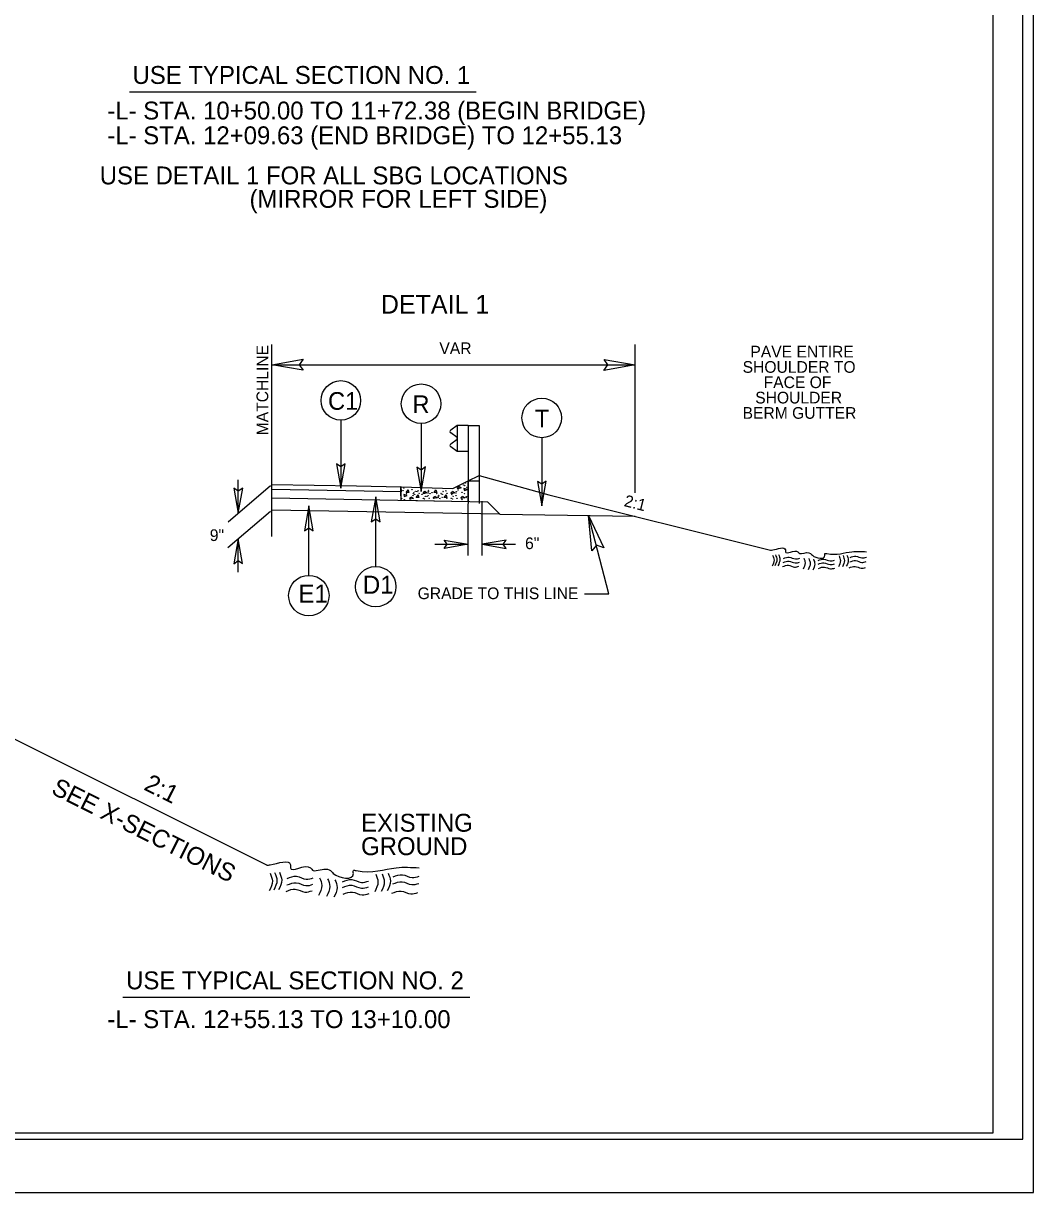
# Model space of a CAD drawing. Extents: x 575722 to 576066, y -53107 to -52774.
# Drawn here: x 575923.44 to 575965.78, y -53106.87 to -53057.85 of the extents above; entities that cross this region are included whole.
import ezdxf

# ---------------------------------------------------------------- set-up
doc = ezdxf.new("R2010")
doc.units = 0
for name, color, linetype in [('Old_Level_1', 7, 'Continuous'), ('Old_Level_11', 7, 'Continuous'), ('Old_Level_2', 7, 'Continuous'), ('Old_Level_20', 7, 'Continuous'), ('Old_Level_21', 7, 'Continuous'), ('Old_Level_3', 7, 'Continuous'), ('Prop Dimension Text', 7, 'Continuous'), ('Prop DSN Text', 7, 'Continuous'), ('Prop Terminator CELL', 7, 'Continuous'), ('Sheet Cutting Line CELL', 7, 'Continuous'), ('Sheet Plot Border Inside CELL', 7, 'Continuous'), ('Sheet Plot Border Outside CELL', 7, 'Continuous'), ('Sheet Typical CELL', 7, 'Continuous'), ('Typical Curb CELL', 7, 'Continuous'), ('Typical Guardrail CELL', 7, 'Continuous'), ('Typical Slope Point Local CELL', 7, 'Continuous'), ('Typical Terminator CELL', 7, 'Continuous'), ('Typical Text Grade Point CELL', 7, 'Continuous')]:
    doc.layers.add(name, color=color, linetype=linetype)

msp = doc.modelspace()

# ---------------------------------------------------------------- linework, layer by layer
at = {"layer": 'Old_Level_1'}
for p, q in [((575933.856, -53077.395), (575933.856, -53077.185)), ((575933.856, -53077.185), (575937.408, -53077.245)), ((575942.087, -53077.033), (575942.551, -53076.801)), ((575942.551, -53076.801), (575945.467, -53077.611)), ((575939.271, -53077.488), (575933.856, -53077.395)), ((575939.268, -53077.276), (575939.268, -53077.854)), ((575945.467, -53077.611), (575954.759, -53079.934)), ((575942.908, -53077.917), (575933.856, -53077.76)), ((575942.908, -53077.917), (575943.413, -53078.421)), ((575943.413, -53078.421), (575933.856, -53078.256)), ((575943.413, -53078.421), (575949.089, -53078.516))]:
    msp.add_line(p, q, dxfattribs=at)
msp.add_lwpolyline([(575937.408, -53077.245), (575939.268, -53077.276), (575939.271, -53077.488)], dxfattribs=at)
at = {"layer": 'Old_Level_11'}
for p, q in [((575942.087, -53080.152), (575942.087, -53077.987)), ((575942.666, -53080.152), (575942.666, -53077.885))]:
    msp.add_line(p, q, dxfattribs=at)
for points in [[(575932.269, -53077.338), (575932.449, -53078.383), (575932.635, -53077.332), (575932.449, -53077.465)], [(575932.269, -53077.338), (575932.449, -53078.383), (575932.635, -53077.332), (575932.449, -53077.465)], [(575932.629, -53080.5), (575932.449, -53079.454), (575932.263, -53080.506), (575932.449, -53080.372)], [(575932.629, -53080.5), (575932.449, -53079.454), (575932.263, -53080.506), (575932.449, -53080.372)]]:
    msp.add_lwpolyline(points, close=True, dxfattribs=at)
at = {"layer": 'Old_Level_2'}
for points in [[(575954.759, -53079.934), (575954.849, -53079.924), (575955.377, -53079.924), (575955.377, -53080), (575955.905, -53080), (575955.981, -53080.075), (575956.056, -53080.075), (575956.434, -53080.075), (575956.509, -53080.151), (575957.037, -53080.151), (575957.037, -53080.075), (575957.113, -53080.075), (575958.169, -53080), (575958.771, -53080)], [(575954.845, -53080.146), (575954.904, -53080.349), (575954.819, -53080.611)], [(575954.963, -53080.129), (575955.022, -53080.332), (575954.938, -53080.594)], [(575955.09, -53080.121), (575955.149, -53080.324), (575955.065, -53080.586)], [(575957.625, -53080.172), (575957.685, -53080.375), (575957.6, -53080.637)], [(575957.794, -53080.163), (575957.854, -53080.366), (575957.769, -53080.628)], [(575957.955, -53080.146), (575958.014, -53080.349), (575957.93, -53080.611)], [(575958.086, -53080.244), (575958.331, -53080.184), (575958.585, -53080.26), (575958.771, -53080.227)], [(575955.263, -53080.624), (575955.508, -53080.565), (575955.762, -53080.641), (575955.948, -53080.607)], [(575955.289, -53080.455), (575955.534, -53080.396), (575955.787, -53080.472), (575955.973, -53080.438)], [(575955.297, -53080.286), (575955.542, -53080.227), (575955.796, -53080.303), (575955.982, -53080.269)], [(575956.146, -53080.265), (575956.206, -53080.467), (575956.121, -53080.73)], [(575956.358, -53080.29), (575956.417, -53080.493), (575956.332, -53080.755)], [(575956.552, -53080.315), (575956.611, -53080.518), (575956.527, -53080.78)], [(575956.751, -53080.37), (575956.996, -53080.311), (575957.249, -53080.387), (575957.435, -53080.353)], [(575956.751, -53080.523), (575956.996, -53080.463), (575957.249, -53080.539), (575957.435, -53080.506)], [(575956.768, -53080.7), (575957.013, -53080.641), (575957.266, -53080.717), (575957.452, -53080.683)], [(575958.052, -53080.675), (575958.297, -53080.615), (575958.551, -53080.692), (575958.737, -53080.658)], [(575958.078, -53080.43), (575958.323, -53080.37), (575958.576, -53080.446), (575958.762, -53080.413)], [(575933.65, -53093.141), (575933.793, -53093.126), (575934.633, -53093.126), (575934.633, -53093.246), (575935.473, -53093.246), (575935.593, -53093.366), (575935.713, -53093.366), (575936.313, -53093.366), (575936.433, -53093.486), (575937.273, -53093.486), (575937.273, -53093.366), (575937.393, -53093.366), (575939.073, -53093.246), (575940.03, -53093.246)], [(575934.176, -53093.439), (575934.27, -53093.761), (575934.136, -53094.178)], [(575933.786, -53093.479), (575933.88, -53093.802), (575933.746, -53094.218)], [(575933.974, -53093.452), (575934.069, -53093.775), (575933.934, -53094.191)], [(575934.492, -53093.97), (575934.882, -53093.876), (575935.285, -53093.997), (575935.581, -53093.943)], [(575934.505, -53093.701), (575934.895, -53093.607), (575935.298, -53093.728), (575935.594, -53093.674)], [(575935.856, -53093.667), (575935.95, -53093.99), (575935.816, -53094.406)], [(575936.192, -53093.707), (575936.286, -53094.03), (575936.152, -53094.447)], [(575936.501, -53093.748), (575936.595, -53094.07), (575936.461, -53094.487)], [(575936.817, -53093.835), (575937.207, -53093.741), (575937.61, -53093.862), (575937.906, -53093.808)], [(575938.208, -53093.519), (575938.302, -53093.842), (575938.168, -53094.259)], [(575938.477, -53093.506), (575938.571, -53093.828), (575938.437, -53094.245)], [(575938.732, -53093.479), (575938.826, -53093.802), (575938.692, -53094.218)], [(575938.927, -53093.929), (575939.317, -53093.835), (575939.72, -53093.956), (575940.016, -53093.902)], [(575938.941, -53093.634), (575939.331, -53093.539), (575939.734, -53093.66), (575940.03, -53093.607)], [(575934.452, -53094.238), (575934.841, -53094.144), (575935.245, -53094.265), (575935.54, -53094.212)], [(575936.817, -53094.077), (575937.207, -53093.983), (575937.61, -53094.104), (575937.906, -53094.05)], [(575936.844, -53094.359), (575937.234, -53094.265), (575937.637, -53094.386), (575937.933, -53094.333)], [(575938.887, -53094.319), (575939.277, -53094.225), (575939.68, -53094.346), (575939.976, -53094.292)]]:
    msp.add_spline(points, degree=3, dxfattribs=at)
at = {"layer": 'Old_Level_21'}
for p, q in [((575933.856, -53079.358), (575933.856, -53071.312)), ((575949.089, -53077.529), (575949.089, -53071.312)), ((575932.022, -53078.747), (575933.803, -53077.231)), ((575932.449, -53078.383), (575932.449, -53076.983)), ((575932.013, -53079.826), (575933.803, -53078.302)), ((575947.976, -53081.769), (575947.122, -53078.483)), ((575932.449, -53080.854), (575932.449, -53079.454)), ((575940.687, -53079.685), (575942.087, -53079.685)), ((575942.666, -53079.685), (575944.066, -53079.685)), ((575946.962, -53081.769), (575947.976, -53081.769))]:
    msp.add_line(p, q, dxfattribs=at)
at = {"layer": 'Prop Dimension Text'}
for p, q in [((575933.856, -53072.166), (575949.089, -53072.166)), ((575936.749, -53074.484), (575936.749, -53077.336)), ((575940.111, -53074.623), (575940.111, -53077.475)), ((575945.165, -53075.22), (575945.165, -53078.072)), ((575938.21, -53080.621), (575938.21, -53077.703)), ((575935.408, -53080.992), (575935.408, -53078.074))]:
    msp.add_line(p, q, dxfattribs=at)
for centre, radius in [((575936.749, -53073.657), 0.828), ((575940.111, -53073.795), 0.828), ((575945.166, -53074.393), 0.828), ((575938.21, -53081.467), 0.847), ((575935.408, -53081.839), 0.847)]:
    msp.add_circle(centre, radius, dxfattribs=at)
at = {"layer": 'Prop DSN Text'}
for p, q in [((575927.887, -53060.719), (575942.418, -53060.719)), ((575927.618, -53098.672), (575942.149, -53098.672))]:
    msp.add_line(p, q, dxfattribs=at)
at = {"layer": 'Prop Terminator CELL'}
for points in [[(575941.084, -53079.512), (575942.087, -53079.685), (575941.078, -53079.864), (575941.206, -53079.685)], [(575943.67, -53079.512), (575942.666, -53079.685), (575943.675, -53079.864), (575943.547, -53079.685)]]:
    msp.add_lwpolyline(points, close=True, dxfattribs=at)
at = {"layer": 'Sheet Cutting Line CELL'}
msp.add_line((575797.38, -53106.867), (575965.78, -53106.867), dxfattribs=at)
at = {"layer": 'Sheet Plot Border Inside CELL'}
msp.add_lwpolyline([(575965.33, -52999.112), (575798.68, -52999.112), (575798.68, -53104.622), (575965.33, -53104.622)], close=True, dxfattribs=at)
at = {"layer": 'Sheet Plot Border Outside CELL'}
msp.add_lwpolyline([(575965.78, -52996.867), (575797.38, -52996.867), (575797.38, -53106.867), (575965.78, -53106.867)], close=True, dxfattribs=at)
at = {"layer": 'Sheet Typical CELL'}
msp.add_lwpolyline([(575964.08, -52999.367), (575814.08, -52999.367), (575814.08, -53104.367), (575964.08, -53104.367)], close=True, dxfattribs=at)
at = {"layer": 'Typical Curb CELL'}
for p, q in [((575941.446, -53077.353), (575942.087, -53077.033)), ((575941.631, -53077.363), (575941.689, -53077.256)), ((575941.689, -53077.256), (575941.785, -53077.326)), ((575942.087, -53077.902), (575942.087, -53077.033)), ((575939.268, -53077.276), (575939.268, -53077.276)), ((575939.268, -53077.664), (575939.268, -53077.286)), ((575939.278, -53077.276), (575941.446, -53077.353)), ((575939.382, -53077.602), (575939.398, -53077.687)), ((575939.526, -53077.644), (575939.382, -53077.602)), ((575939.398, -53077.687), (575939.526, -53077.644)), ((575939.49, -53077.523), (575939.571, -53077.411)), ((575939.603, -53077.517), (575939.49, -53077.523)), ((575939.571, -53077.411), (575939.603, -53077.517)), ((575939.642, -53077.801), (575939.7, -53077.694)), ((575939.7, -53077.694), (575939.796, -53077.764)), ((575939.91, -53077.727), (575939.991, -53077.615)), ((575940.023, -53077.721), (575939.91, -53077.727)), ((575939.991, -53077.615), (575940.023, -53077.721)), ((575940.204, -53077.57), (575940.263, -53077.463)), ((575940.359, -53077.533), (575940.204, -53077.57)), ((575940.263, -53077.463), (575940.359, -53077.533)), ((575940.625, -53077.774), (575940.683, -53077.667)), ((575940.779, -53077.737), (575940.625, -53077.774)), ((575940.656, -53077.523), (575940.736, -53077.411)), ((575940.768, -53077.517), (575940.656, -53077.523)), ((575940.683, -53077.667), (575940.779, -53077.737)), ((575940.736, -53077.411), (575940.768, -53077.517)), ((575941.077, -53077.727), (575941.157, -53077.615)), ((575941.189, -53077.721), (575941.077, -53077.727)), ((575941.157, -53077.615), (575941.189, -53077.721)), ((575941.37, -53077.57), (575941.428, -53077.463)), ((575941.524, -53077.533), (575941.37, -53077.57)), ((575941.428, -53077.463), (575941.524, -53077.533)), ((575941.785, -53077.326), (575941.631, -53077.363)), ((575941.79, -53077.774), (575941.849, -53077.667)), ((575941.945, -53077.737), (575941.79, -53077.774)), ((575941.849, -53077.667), (575941.945, -53077.737)), ((575941.909, -53077.344), (575941.925, -53077.428)), ((575942.053, -53077.386), (575941.909, -53077.344)), ((575941.925, -53077.428), (575942.053, -53077.386)), ((575942.087, -53077.902), (575939.268, -53077.854)), ((575939.796, -53077.764), (575939.642, -53077.801))]:
    msp.add_line(p, q, dxfattribs=at)
for centre in [(575941.891, -53077.201), (575941.943, -53077.233), (575941.974, -53077.115), (575939.352, -53077.442), (575939.388, -53077.325), (575939.5, -53077.564), (575939.649, -53077.749), (575939.73, -53077.394), (575939.773, -53077.645), (575939.786, -53077.561), (575939.808, -53077.528), (575939.838, -53077.593), (575939.869, -53077.474), (575939.939, -53077.476), (575939.986, -53077.448), (575940.03, -53077.556), (575940.151, -53077.598), (575940.206, -53077.765), (575940.211, -53077.519), (575940.289, -53077.678), (575940.36, -53077.68), (575940.403, -53077.534), (575940.407, -53077.652), (575940.419, -53077.487), (575940.428, -53077.432), (575940.45, -53077.759), (575940.481, -53077.565), (575940.571, -53077.522), (575940.632, -53077.723), (575940.658, -53077.514), (575940.77, -53077.561), (575940.823, -53077.738), (575940.839, -53077.691), (575940.849, -53077.636), (575940.952, -53077.561), (575940.992, -53077.726), (575941.004, -53077.593), (575941.035, -53077.474), (575941.079, -53077.717), (575941.152, -53077.448), (575941.191, -53077.765), (575941.196, -53077.556), (575941.372, -53077.765), (575941.377, -53077.519), (575941.403, -53077.614), (575941.455, -53077.678), (575941.569, -53077.534), (575941.572, -53077.652), (575941.585, -53077.487), (575941.616, -53077.759), (575941.638, -53077.312), (575941.664, -53077.407), (575941.797, -53077.723), (575941.824, -53077.514), (575941.936, -53077.561), (575941.989, -53077.738), (575942.005, -53077.691), (575942.027, -53077.306), (575939.297, -53077.772), (575939.409, -53077.819), (575939.675, -53077.844), (575940.259, -53077.796), (575940.902, -53077.769), (575941.424, -53077.796), (575941.824, -53077.818)]:
    msp.add_circle(centre, 0.00749, dxfattribs=at)
msp.add_arc((575939.278, -53077.286), 0.00972, 87.952, 180, dxfattribs=at)
at = {"layer": 'Typical Guardrail CELL'}
for p, q in [((575941.623, -53074.713), (575941.353, -53074.902)), ((575942.087, -53074.713), (575941.623, -53074.713)), ((575941.623, -53074.713), (575941.623, -53075.795)), ((575942.087, -53074.713), (575942.087, -53077.033)), ((575942.087, -53074.713), (575942.551, -53074.713)), ((575942.551, -53074.713), (575942.551, -53077.033)), ((575941.623, -53075.21), (575941.353, -53075.021)), ((575941.623, -53075.298), (575941.353, -53075.487)), ((575941.623, -53075.254), (575941.623, -53075.21)), ((575941.623, -53075.254), (575941.623, -53075.298)), ((575941.623, -53075.795), (575941.353, -53075.606)), ((575942.087, -53075.795), (575941.623, -53075.795)), ((575942.087, -53077.033), (575942.551, -53077.033)), ((575942.087, -53077.033), (575942.087, -53077.974)), ((575942.551, -53077.033), (575942.551, -53077.974))]:
    msp.add_line(p, q, dxfattribs=at)
for centre, start, end in [((575941.394, -53074.962), 125.003, 235.0112), ((575941.394, -53075.546), 125.0059, 235.0366)]:
    msp.add_arc(centre, 0.0725, start, end, dxfattribs=at)
at = {"layer": 'Typical Slope Point Local CELL'}
msp.add_line((575933.65, -53093.141), (575922.488, -53087.56), dxfattribs=at)
at = {"layer": 'Typical Terminator CELL'}
for points in [[(575935.163, -53072.391), (575933.856, -53072.166), (575935.17, -53071.933), (575935.003, -53072.166)], [(575947.782, -53071.941), (575949.089, -53072.166), (575947.775, -53072.398), (575947.942, -53072.166)], [(575936.573, -53076.315), (575936.749, -53077.336), (575936.931, -53076.309), (575936.749, -53076.439)], [(575939.935, -53076.453), (575940.111, -53077.475), (575940.293, -53076.447), (575940.111, -53076.578)], [(575944.989, -53077.05), (575945.165, -53078.072), (575945.347, -53077.045), (575945.165, -53077.175)], [(575938.391, -53078.748), (575938.21, -53077.703), (575938.025, -53078.754), (575938.21, -53078.621)], [(575935.588, -53079.12), (575935.408, -53078.074), (575935.222, -53079.125), (575935.408, -53078.992)], [(575947.268, -53079.968), (575947.122, -53078.483), (575947.767, -53079.839), (575947.465, -53079.727)]]:
    msp.add_lwpolyline(points, close=True, dxfattribs=at)

# ---------------------------------------------------------------- texts
at = {"layer": 'Old_Level_11'}
msp.add_text('6" ', height=0.49, rotation=359.9966, dxfattribs=at).set_placement((575944.469, -53079.891))
at = {"layer": 'Old_Level_20'}
for s, height, p in [('C1', 0.7408, (575936.212, -53074.05)), ('R', 0.741, (575939.75, -53074.189)), ('T', 0.741, (575944.875, -53074.786)), ('D1', 0.7579, (575937.667, -53081.763)), ('E1', 0.7579, (575934.968, -53082.134))]:
    msp.add_text(s, height=height, dxfattribs=at).set_placement(p)
at = {"layer": 'Old_Level_21'}
for s, height, p in [('USE DETAIL 1 FOR ALL SBG LOCATIONS', 0.75, (575926.644, -53064.601)), (' (MIRROR FOR LEFT SIDE)', 0.75, (575932.644, -53065.584)), ('VAR', 0.49, (575940.878, -53071.716)), ('PAVE ENTIRE', 0.49, (575953.912, -53071.858)), ('SHOULDER TO', 0.49, (575953.587, -53072.5)), ('FACE OF', 0.49, (575954.467, -53073.142)), (' SHOULDER', 0.49, (575953.932, -53073.785)), ('BERM GUTTER', 0.49, (575953.585, -53074.427)), ('GRADE TO THIS LINE', 0.49, (575939.968, -53081.988))]:
    msp.add_text(s, height=height, dxfattribs=at).set_placement(p)
for s, rotation, p in [('MATCHLINE', 90, (575933.705, -53075.119)), (' 2:1', 345.6047, (575948.41, -53078.036))]:
    msp.add_text(s, height=0.49, rotation=rotation, dxfattribs=at).set_placement(p)
at = {"layer": 'Old_Level_3'}
msp.add_text('DETAIL 1', height=0.784, dxfattribs=at).set_placement((575938.424, -53070.019))
at = {"layer": 'Prop Dimension Text'}
msp.add_text('9"', height=0.49, dxfattribs=at).set_placement((575931.256, -53079.552))
at = {"layer": 'Prop DSN Text'}
for s, p in [('USE TYPICAL SECTION NO. 1', (575928.018, -53060.39)), ('-L- STA. 10+50.00 TO 11+72.38 (BEGIN BRIDGE)', (575926.963, -53061.881)), ('-L- STA. 12+09.63 (END BRIDGE) TO 12+55.13', (575926.963, -53062.919)), ('USE TYPICAL SECTION NO. 2', (575927.749, -53098.344)), ('-L- STA. 12+55.13 TO 13+10.00', (575926.963, -53099.969))]:
    msp.add_text(s, height=0.75, dxfattribs=at).set_placement(p)
at = {"layer": 'Typical Slope Point Local CELL'}
for s, p in [('2:1', (575928.453, -53089.959)), ('SEE X-SECTIONS', (575924.568, -53090.123))]:
    msp.add_text(s, height=0.75, rotation=333.434, dxfattribs=at).set_placement(p)
at = {"layer": 'Typical Text Grade Point CELL'}
for s, p in [('EXISTING', (575937.596, -53091.737)), ('GROUND', (575937.596, -53092.72))]:
    msp.add_text(s, height=0.75, dxfattribs=at).set_placement(p)

doc.saveas('drawing.dxf')
